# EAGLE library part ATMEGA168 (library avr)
MICROCONTROLLER 16 kBytes FLASH 1 kBytes SRAM 512 Bytes EEPROM USART 8-channel 10 bit ADC
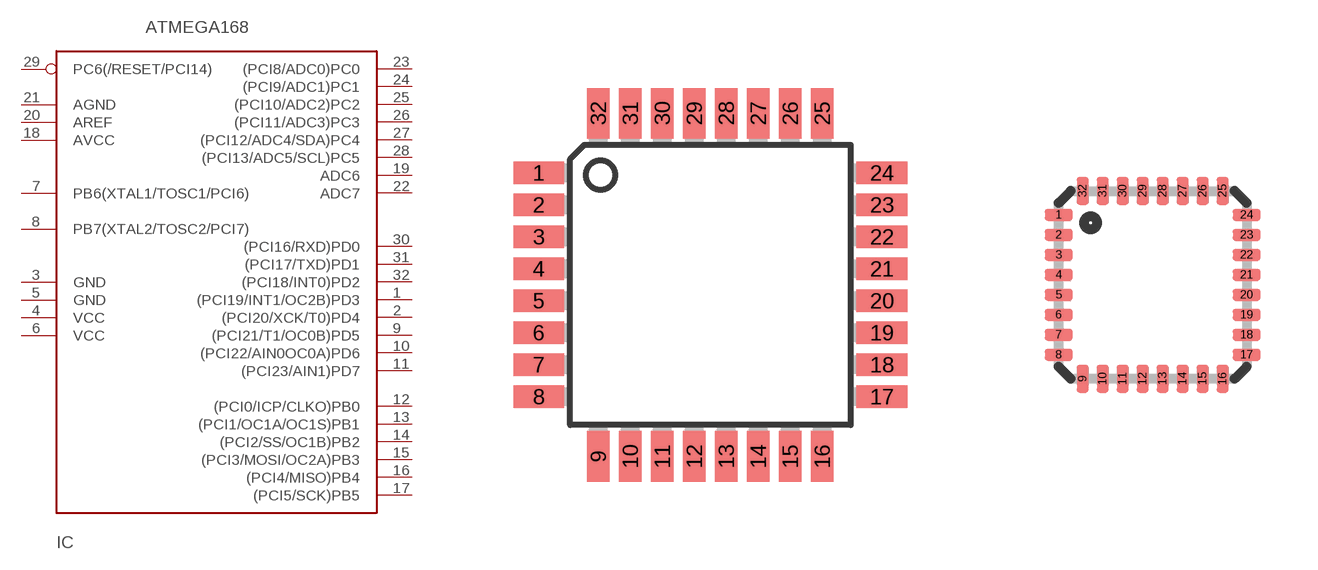
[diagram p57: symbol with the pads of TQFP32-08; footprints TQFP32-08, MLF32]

Designator prefix IC

## ATMEGA168-20A, ATMEGA168V-10A  [TQFP32-08]
1  (PCI19/INT1/OC2B)PD3
2  (PCI20/XCK/T0)PD4
3  GND  pwr
4  VCC  pwr
5  GND  pwr
6  VCC  pwr
7  PB6(XTAL1/TOSC1/PCI6)
8  PB7(XTAL2/TOSC2/PCI7)
9  (PCI21/T1/OC0B)PD5
10  (PCI22/AIN0OC0A)PD6
11  (PCI23/AIN1)PD7
12  (PCI0/ICP/CLKO)PB0
13  (PCI1/OC1A/OC1S)PB1
14  (PCI2/SS/OC1B)PB2
15  (PCI3/MOSI/OC2A)PB3
16  (PCI4/MISO)PB4
17  (PCI5/SCK)PB5
18  AVCC
19  ADC6
20  AREF
21  AGND
22  ADC7
23  (PCI8/ADC0)PC0
24  (PCI9/ADC1)PC1
25  (PCI10/ADC2)PC2
26  (PCI11/ADC3)PC3
27  (PCI12/ADC4/SDA)PC4
28  (PCI13/ADC5/SCL)PC5
29  PC6(/RESET/PCI14)
30  (PCI16/RXD)PD0
31  (PCI17/TXD)PD1
32  (PCI18/INT0)PD2

## ATMEGA168-20M, ATMEGA168V-10M  [MLF32]
Pads as for TQFP32-08

## Footprint TQFP32-08 (pad centres in mm)
Thin Plasic Quad Flat Package Grid 0.8 mm
smd 1.27 x 0.559: 1 -4.293,2.8; 2 -4.293,2; 3 -4.293,1.2; 4 -4.293,0.4; 5 -4.293,-0.4; 6 -4.293,-1.2; 7 -4.293,-2; 8 -4.293,-2.8; 17 4.293,-2.8; 18 4.293,-2; 19 4.293,-1.2; 20 4.293,-0.4; 21 4.293,0.4; 22 4.293,1.2; 23 4.293,2; 24 4.293,2.8
smd 0.559 x 1.27: 9 -2.8,-4.293; 10 -2,-4.293; 11 -1.2,-4.293; 12 -0.4,-4.293; 13 0.4,-4.293; 14 1.2,-4.293; 15 2,-4.293; 16 2.8,-4.293; 25 2.8,4.293; 26 2,4.293; 27 1.2,4.293; 28 0.4,4.293; 29 -0.4,4.293; 30 -1.2,4.293; 31 -2,4.293; 32 -2.8,4.293

## Footprint MLF32 (pad centres in mm)
32M1-A Micro Lead Frame package (MLF)
smd 0.7 x 0.3: 1 -2.35,1.75; 2 -2.35,1.25; 3 -2.35,0.75; 4 -2.35,0.25; 5 -2.35,-0.25; 6 -2.35,-0.75; 7 -2.35,-1.25; 8 -2.35,-1.75; 17 2.35,-1.75; 18 2.35,-1.25; 19 2.35,-0.75; 20 2.35,-0.25; 21 2.35,0.25; 22 2.35,0.75; 23 2.35,1.25; 24 2.35,1.75
smd 0.3 x 0.7: 9 -1.75,-2.35; 10 -1.25,-2.35; 11 -0.75,-2.35; 12 -0.25,-2.35; 13 0.25,-2.35; 14 0.75,-2.35; 15 1.25,-2.35; 16 1.75,-2.35; 25 1.75,2.35; 26 1.25,2.35; 27 0.75,2.35; 28 0.25,2.35; 29 -0.25,2.35; 30 -0.75,2.35; 31 -1.25,2.35; 32 -1.75,2.35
